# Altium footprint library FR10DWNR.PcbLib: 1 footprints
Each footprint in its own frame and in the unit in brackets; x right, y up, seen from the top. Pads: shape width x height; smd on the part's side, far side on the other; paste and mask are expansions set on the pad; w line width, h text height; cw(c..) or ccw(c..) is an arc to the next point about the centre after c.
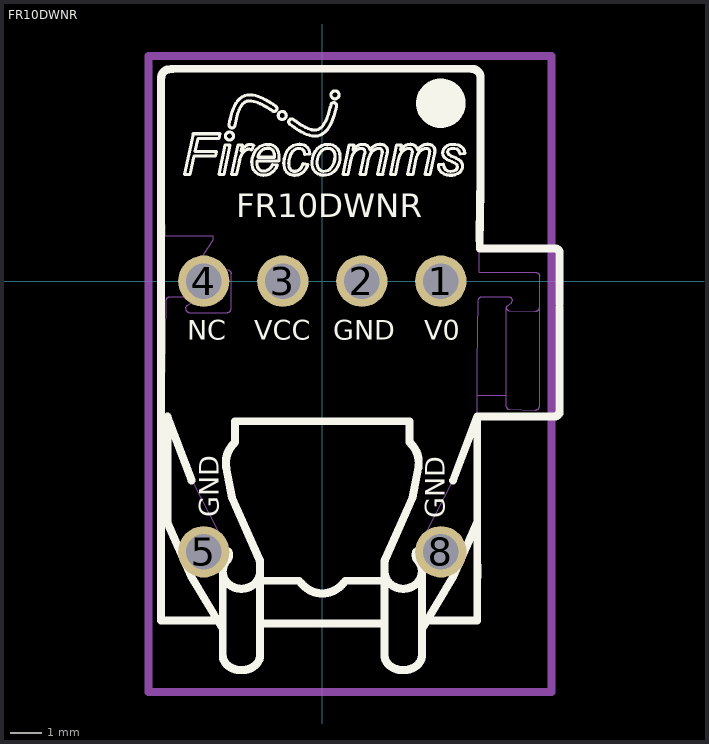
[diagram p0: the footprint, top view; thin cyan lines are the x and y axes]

## FR10DWNR [mil] "Non-Inverting RedLink® 10 MBd Receiver Tilted"
height 600
pads (6):
  round 65 hole 45: 1(150,0) 2(50,0) 3(-50,0) 4(-150,0) 5(-150,-342.52) 8(150,-342.52)
Top Overlay:
  drawing of 2404 lines, arcs and shapes, not listed
  text "FR10DWNR" at -109,81 h30
  text "GND" at -131,-299 h25
  text "GND" at 155,-300 h25
  text "V0" at 129,-74 h25
  text "GND" at 14,-74 h25
  text "VCC" at -86,-74 h25
  text "NC" at -171,-74 h25
Mechanical 2:
  lines w10: -220,-520 -220,285 290,285 290,-520 -220,-520
Mechanical 19:
  drawing of 2824 lines, arcs and shapes, not listed
3D body "Tiltet.stp": height 633.84, standoff -337.66, extent -205,-721.77 273.74,268.47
